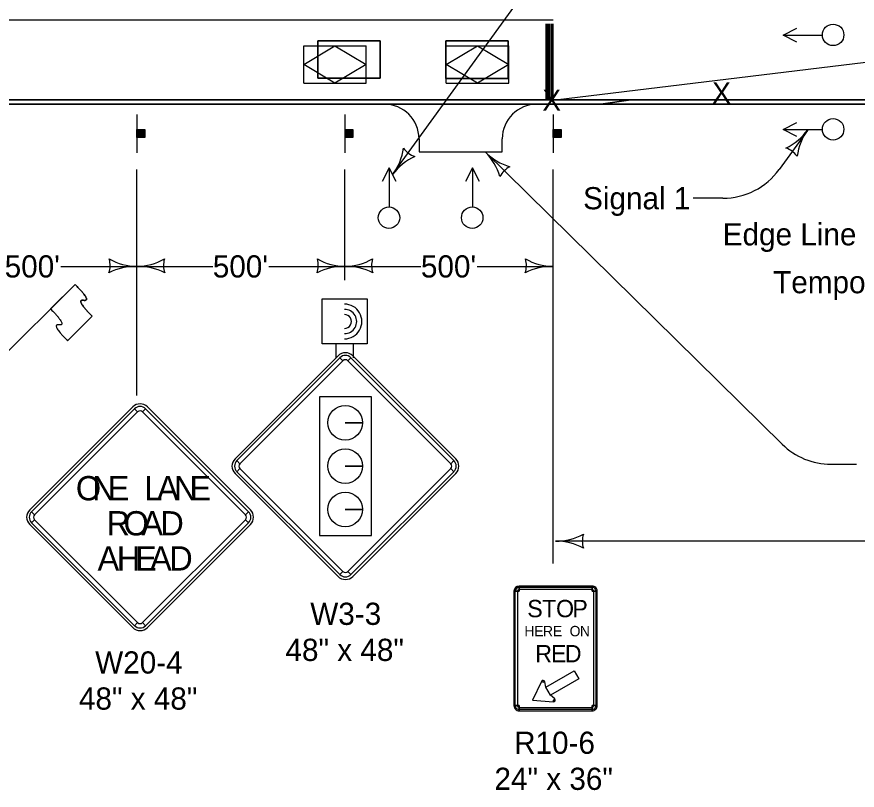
# Model space of a CAD drawing. Extents: x -2134934 to -2122394, y -2139046 to -2137036.
# Drawn here: x -2129918 to -2129313, y -2138163 to -2137605 of the extents above; entities that cross this region are included whole.
import ezdxf

# ---------------------------------------------------------------- set-up
doc = ezdxf.new("R2010")
doc.units = 0
for name, color, linetype in [('Barrier', 7, 'Continuous'), ('BridgeSuperStructureExisting', 7, 'Continuous'), ('DsnShtPlotIdentification', 7, 'Continuous'), ('DsnShtPlotShape', 7, 'Continuous'), ('dsnTextFinalPlan', 7, 'Continuous'), ('TC_Barrier', 7, 'Continuous')]:
    doc.layers.add(name, color=color, linetype=linetype)

msp = doc.modelspace()

# ---------------------------------------------------------------- linework, layer by layer
at = {"layer": 'Barrier'}
for p, q in [((-2129933.82, -2137855.42), (-2129876.5, -2137798.11)), ((-2129876.5, -2137798.11), (-2129894.18, -2137815.79)), ((-2129881.8, -2137838.78), (-2129864.12, -2137821.1)), ((-2129686.95, -2137849.65), (-2129761.19, -2137923.9)), ((-2129685.62, -2137850.98), (-2129683.41, -2137853.19)), ((-2129679.88, -2137853.19), (-2129677.67, -2137850.98)), ((-2129602.1, -2137923.9), (-2129676.34, -2137849.65)), ((-2129834.91, -2137886.48), (-2129909.16, -2137960.72)), ((-2129833.59, -2137887.8), (-2129831.38, -2137890.01)), ((-2129827.84, -2137890.01), (-2129825.63, -2137887.8)), ((-2129750.06, -2137960.72), (-2129824.31, -2137886.48)), ((-2129669.24, -2137897.87), (-2129681.74, -2137897.87)), ((-2129681.74, -2137897.87), (-2129669.24, -2137897.87)), ((-2129757.66, -2137927.43), (-2129759.87, -2137925.22)), ((-2129669.24, -2137929.12), (-2129681.74, -2137929.12)), ((-2129681.74, -2137929.12), (-2129669.24, -2137929.12)), ((-2129603.42, -2137925.22), (-2129605.63, -2137927.43)), ((-2129761.19, -2137934.5), (-2129686.95, -2138008.75)), ((-2129759.87, -2137933.18), (-2129757.66, -2137930.97)), ((-2129676.34, -2138008.75), (-2129602.1, -2137934.5)), ((-2129605.63, -2137930.97), (-2129603.42, -2137933.18)), ((-2129669.24, -2137960.37), (-2129681.74, -2137960.37)), ((-2129681.74, -2137960.37), (-2129669.24, -2137960.37)), ((-2129905.62, -2137964.26), (-2129907.83, -2137962.05)), ((-2129751.39, -2137962.05), (-2129753.59, -2137964.26)), ((-2129909.16, -2137971.33), (-2129834.91, -2138045.58)), ((-2129907.83, -2137970.01), (-2129905.62, -2137967.8)), ((-2129824.31, -2138045.58), (-2129750.06, -2137971.33)), ((-2129753.59, -2137967.8), (-2129751.39, -2137970.01)), ((-2129683.41, -2138005.21), (-2129685.62, -2138007.42)), ((-2129677.67, -2138007.42), (-2129679.88, -2138005.21)), ((-2129560.12, -2138019.4), (-2129556.37, -2138019.4)), ((-2129559.18, -2138019.4), (-2129557.62, -2138019.4)), ((-2129556.37, -2138019.4), (-2129556.37, -2138015.65)), ((-2129556.37, -2138018.15), (-2129556.37, -2138016.58)), ((-2129503.87, -2138015.65), (-2129503.87, -2138019.4)), ((-2129503.87, -2138016.58), (-2129503.87, -2138018.15)), ((-2129503.87, -2138019.4), (-2129500.12, -2138019.4)), ((-2129502.62, -2138019.4), (-2129501.05, -2138019.4)), ((-2129831.38, -2138042.04), (-2129833.59, -2138044.25)), ((-2129825.63, -2138044.25), (-2129827.84, -2138042.04)), ((-2129540.26, -2138084.38), (-2129539.15, -2138084.96)), ((-2129539.15, -2138084.96), (-2129537.93, -2138084.69)), ((-2129531.65, -2138097.95), (-2129531.7, -2138099.2)), ((-2129530.8, -2138097.03), (-2129531.65, -2138097.95)), ((-2129556.37, -2138101.9), (-2129560.12, -2138101.9)), ((-2129557.62, -2138101.9), (-2129559.18, -2138101.9)), ((-2129556.37, -2138105.65), (-2129556.37, -2138101.9)), ((-2129556.37, -2138104.71), (-2129556.37, -2138103.15)), ((-2129500.12, -2138101.9), (-2129503.87, -2138101.9)), ((-2129503.87, -2138101.9), (-2129503.87, -2138105.65)), ((-2129503.87, -2138103.15), (-2129503.87, -2138104.71)), ((-2129501.05, -2138101.9), (-2129502.62, -2138101.9))]:
    msp.add_line(p, q, dxfattribs=at)
for points in [[(-2129685.62, -2137850.98), (-2129759.87, -2137925.22), (-2129757.66, -2137927.43), (-2129683.41, -2137853.19), (-2129685.62, -2137850.98)], [(-2129603.42, -2137925.22), (-2129677.67, -2137850.98), (-2129679.88, -2137853.19), (-2129605.63, -2137927.43), (-2129603.42, -2137925.22)], [(-2129662.91, -2137879.26), (-2129700.38, -2137879.26), (-2129700.38, -2137979.15), (-2129662.91, -2137979.15), (-2129662.91, -2137879.26)], [(-2129833.59, -2137887.8), (-2129907.83, -2137962.05), (-2129905.62, -2137964.26), (-2129831.38, -2137890.01), (-2129833.59, -2137887.8)], [(-2129751.39, -2137962.05), (-2129825.63, -2137887.8), (-2129827.84, -2137890.01), (-2129753.59, -2137964.26), (-2129751.39, -2137962.05)], [(-2129759.87, -2137933.18), (-2129685.62, -2138007.42), (-2129683.41, -2138005.21), (-2129757.66, -2137930.97), (-2129759.87, -2137933.18)], [(-2129677.67, -2138007.42), (-2129603.42, -2137933.18), (-2129605.63, -2137930.97), (-2129679.88, -2138005.21), (-2129677.67, -2138007.42)], [(-2129907.83, -2137970.01), (-2129833.59, -2138044.25), (-2129831.38, -2138042.04), (-2129905.62, -2137967.8), (-2129907.83, -2137970.01)], [(-2129825.63, -2138044.25), (-2129751.39, -2137970.01), (-2129753.59, -2137967.8), (-2129827.84, -2138042.04), (-2129825.63, -2138044.25)], [(-2129556.37, -2138105.65), (-2129503.87, -2138105.65), (-2129503.87, -2138101.9), (-2129500.12, -2138101.9), (-2129500.12, -2138019.4), (-2129503.87, -2138019.4), (-2129503.87, -2138015.65), (-2129556.37, -2138015.65), (-2129556.37, -2138019.4), (-2129560.12, -2138019.4), (-2129560.12, -2138101.9), (-2129556.37, -2138101.9), (-2129556.37, -2138105.65)], [(-2129557.62, -2138019.4), (-2129557.62, -2138101.9), (-2129559.18, -2138101.9), (-2129559.18, -2138019.4), (-2129557.62, -2138019.4)], [(-2129503.87, -2138018.15), (-2129556.37, -2138018.15), (-2129556.37, -2138016.58), (-2129503.87, -2138016.58), (-2129503.87, -2138018.15)], [(-2129502.62, -2138101.9), (-2129502.62, -2138019.4), (-2129501.05, -2138019.4), (-2129501.05, -2138101.9), (-2129502.62, -2138101.9)], [(-2129516.74, -2138076.9), (-2129513.46, -2138082.58), (-2129533.77, -2138094.3), (-2129537.05, -2138088.62), (-2129516.74, -2138076.9)], [(-2129546.77, -2138098.02), (-2129531.7, -2138099.2), (-2129531.65, -2138097.95), (-2129530.8, -2138097.03), (-2129533.77, -2138094.3), (-2129537.05, -2138088.62), (-2129537.93, -2138084.69), (-2129539.15, -2138084.96), (-2129540.26, -2138084.38), (-2129546.77, -2138098.02)], [(-2129556.37, -2138103.15), (-2129503.87, -2138103.15), (-2129503.87, -2138104.71), (-2129556.37, -2138104.71), (-2129556.37, -2138103.15)]]:
    msp.add_lwpolyline(points, close=True, dxfattribs=at)
for centre in [(-2129681.74, -2137897.87), (-2129681.74, -2137929.12), (-2129681.74, -2137960.37)]:
    msp.add_circle(centre, 12.5, dxfattribs=at)
for centre, radius, start, end in [((-2129681.64, -2137854.96), 7.5, 44.99999, 134.99974), ((-2129681.64, -2137854.96), 5.62, 44.99999, 134.99974), ((-2129681.64, -2137854.96), 2.5, 44.99999, 134.99974), ((-2129829.61, -2137891.78), 7.5, 44.99999, 134.99974), ((-2129829.61, -2137891.78), 5.62, 44.99999, 134.99974), ((-2129829.61, -2137891.78), 2.5, 44.99999, 134.99974), ((-2129755.89, -2137929.2), 7.5, 134.99974, 224.99995), ((-2129607.4, -2137929.2), 7.5, 315.00016, 44.9998), ((-2129755.89, -2137929.2), 5.62, 134.99974, 224.99995), ((-2129755.89, -2137929.2), 2.5, 134.99974, 224.99995), ((-2129607.4, -2137929.2), 2.5, 315.00016, 44.9998), ((-2129607.4, -2137929.2), 5.62, 315.00016, 44.9998), ((-2129903.85, -2137966.03), 7.5, 134.99974, 224.99995), ((-2129755.36, -2137966.03), 7.5, 315.00016, 44.9998), ((-2129903.85, -2137966.03), 5.62, 134.99974, 224.99995), ((-2129903.85, -2137966.03), 2.5, 134.99974, 224.99995), ((-2129755.36, -2137966.03), 2.5, 315.00016, 44.9998), ((-2129755.36, -2137966.03), 5.62, 315.00016, 44.9998), ((-2129681.64, -2138003.45), 7.5, 224.99995, 315.00016), ((-2129681.64, -2138003.45), 5.62, 224.99995, 315.00016), ((-2129681.64, -2138003.45), 2.5, 224.99995, 315.00016), ((-2129556.37, -2138019.4), 3.75, 90.00021, 179.99985), ((-2129556.37, -2138019.4), 2.81, 90.00021, 179.99985), ((-2129556.37, -2138019.4), 1.25, 90.00021, 179.99985), ((-2129503.87, -2138019.4), 3.75, 0, 90.00021), ((-2129503.87, -2138019.4), 2.81, 0, 90.00021), ((-2129503.87, -2138019.4), 1.25, 0, 90.00021), ((-2129829.61, -2138040.27), 5.62, 224.99995, 315.00016), ((-2129829.61, -2138040.27), 2.5, 224.99995, 315.00016), ((-2129829.61, -2138040.27), 7.5, 224.99995, 315.00016), ((-2129539.15, -2138084.96), 1.25, 12.62232, 152.27557), ((-2129531.65, -2138097.95), 1.25, 267.72427, 47.37758), ((-2129556.37, -2138101.9), 3.75, 179.99985, 270.00006), ((-2129556.37, -2138101.9), 2.81, 179.99985, 270.00006), ((-2129556.37, -2138101.9), 1.25, 179.99985, 270.00006), ((-2129503.87, -2138101.9), 3.75, 270.00006, 0.00027), ((-2129503.87, -2138101.9), 2.81, 270.00006, 0.00027), ((-2129503.87, -2138101.9), 1.25, 270.00006, 0.00027)]:
    msp.add_arc(centre, radius, start, end, dxfattribs=at)
for points in [[(-2129864.12, -2137821.1), (-2129876.5, -2137808.72), (-2129864.12, -2137810.49), (-2129876.5, -2137798.11)], [(-2129894.18, -2137815.79), (-2129881.8, -2137828.17), (-2129894.17, -2137826.4), (-2129881.8, -2137838.78)]]:
    msp.add_open_spline(points, degree=2, dxfattribs=at)
at = {"layer": 'BridgeSuperStructureExisting'}
for p, q in [((-2129647.56, -2137718.98), (-2129506.09, -2137523.28)), ((-2129530.12, -2137665.16), (-2129039.8, -2137605.17)), ((-2129536.95, -2137665.16), (-2129536.95, -2137610.16)), ((-2129535.95, -2137665.16), (-2129535.95, -2137610.16)), ((-2129534.95, -2137665.16), (-2129534.95, -2137610.16)), ((-2129533.95, -2137665.16), (-2129533.95, -2137610.16)), ((-2129532.95, -2137665.16), (-2129532.95, -2137610.16)), ((-2129531.95, -2137665.16), (-2129531.95, -2137610.16)), ((-2129337.85, -2137618.58), (-2129365.8, -2137618.58)), ((-2129711.63, -2137653.13), (-2129711.63, -2137626.13)), ((-2129711.63, -2137626.13), (-2129666.63, -2137626.13)), ((-2129701.47, -2137622.46), (-2129656.47, -2137622.46)), ((-2129701.47, -2137649.46), (-2129701.47, -2137622.46)), ((-2129656.47, -2137622.46), (-2129701.47, -2137622.46)), ((-2129701.47, -2137622.46), (-2129701.47, -2137649.46)), ((-2129666.63, -2137653.13), (-2129666.63, -2137626.13)), ((-2129656.47, -2137622.46), (-2129656.47, -2137649.46)), ((-2129656.47, -2137649.46), (-2129656.47, -2137622.46)), ((-2129609.28, -2137622.54), (-2129564.28, -2137622.54)), ((-2129609.28, -2137649.54), (-2129609.28, -2137622.54)), ((-2129564.28, -2137622.54), (-2129609.28, -2137622.54)), ((-2129609.28, -2137622.54), (-2129609.28, -2137649.54)), ((-2129608.95, -2137653.13), (-2129608.95, -2137626.13)), ((-2129608.95, -2137626.13), (-2129563.95, -2137626.13)), ((-2129564.28, -2137622.54), (-2129564.28, -2137649.54)), ((-2129564.28, -2137649.54), (-2129564.28, -2137622.54)), ((-2129563.95, -2137653.13), (-2129563.95, -2137626.13)), ((-2129656.47, -2137649.46), (-2129701.47, -2137649.46)), ((-2129701.47, -2137649.46), (-2129656.47, -2137649.46)), ((-2129564.28, -2137649.54), (-2129609.28, -2137649.54)), ((-2129609.28, -2137649.54), (-2129564.28, -2137649.54)), ((-2129711.63, -2137653.13), (-2129666.63, -2137653.13)), ((-2129608.95, -2137653.13), (-2129563.95, -2137653.13)), ((-2130182.57, -2137665.16), (-2128870.12, -2137665.16)), ((-2129543.56, -2137668.16), (-2129653.56, -2137668.16)), ((-2129639.46, -2137668.16), (-2129614.46, -2137668.16)), ((-2129831.95, -2137675.66), (-2129831.95, -2137703.16)), ((-2129681.95, -2137675.66), (-2129681.95, -2137703.16)), ((-2129531.95, -2137675.66), (-2129531.95, -2137703.16)), ((-2129831.54, -2137692.11), (-2129831.54, -2137686.52)), ((-2129831.26, -2137686.52), (-2129831.26, -2137692.11)), ((-2129830.99, -2137692.11), (-2129830.99, -2137686.52)), ((-2129830.73, -2137686.52), (-2129830.73, -2137692.11)), ((-2129830.51, -2137692.11), (-2129830.51, -2137686.52)), ((-2129830.3, -2137686.52), (-2129830.3, -2137692.11)), ((-2129829.96, -2137692.11), (-2129829.96, -2137686.52)), ((-2129829.7, -2137686.52), (-2129829.7, -2137692.11)), ((-2129829.47, -2137692.11), (-2129829.49, -2137686.52)), ((-2129829.16, -2137686.52), (-2129829.16, -2137692.11)), ((-2129828.78, -2137692.11), (-2129828.78, -2137686.52)), ((-2129828.35, -2137686.52), (-2129828.35, -2137692.11)), ((-2129828.12, -2137692.11), (-2129828.14, -2137686.52)), ((-2129827.71, -2137686.52), (-2129827.69, -2137692.11)), ((-2129827.49, -2137692.11), (-2129827.49, -2137686.52)), ((-2129827.17, -2137686.52), (-2129827.17, -2137692.11)), ((-2129826.94, -2137692.11), (-2129826.94, -2137686.52)), ((-2129826.62, -2137686.52), (-2129826.62, -2137692.11)), ((-2129681.54, -2137692.11), (-2129681.54, -2137686.52)), ((-2129681.26, -2137686.52), (-2129681.26, -2137692.11)), ((-2129680.99, -2137692.11), (-2129680.99, -2137686.52)), ((-2129680.73, -2137686.52), (-2129680.73, -2137692.11)), ((-2129680.51, -2137692.11), (-2129680.51, -2137686.52)), ((-2129680.3, -2137686.52), (-2129680.3, -2137692.11)), ((-2129679.96, -2137692.11), (-2129679.96, -2137686.52)), ((-2129679.7, -2137686.52), (-2129679.7, -2137692.11)), ((-2129679.48, -2137692.11), (-2129679.49, -2137686.52)), ((-2129679.16, -2137686.52), (-2129679.16, -2137692.11)), ((-2129678.78, -2137692.11), (-2129678.78, -2137686.52)), ((-2129678.35, -2137686.52), (-2129678.35, -2137692.11)), ((-2129678.13, -2137692.11), (-2129678.14, -2137686.52)), ((-2129677.71, -2137686.52), (-2129677.69, -2137692.11)), ((-2129677.49, -2137692.11), (-2129677.49, -2137686.52)), ((-2129677.17, -2137686.52), (-2129677.17, -2137692.11)), ((-2129676.94, -2137692.11), (-2129676.94, -2137686.52)), ((-2129676.63, -2137686.52), (-2129676.63, -2137692.11)), ((-2129531.54, -2137692.11), (-2129531.54, -2137686.52)), ((-2129531.26, -2137686.52), (-2129531.26, -2137692.11)), ((-2129530.99, -2137692.11), (-2129530.99, -2137686.52)), ((-2129530.73, -2137686.52), (-2129530.73, -2137692.11)), ((-2129530.51, -2137692.11), (-2129530.51, -2137686.52)), ((-2129530.3, -2137686.52), (-2129530.3, -2137692.11)), ((-2129529.96, -2137692.11), (-2129529.96, -2137686.52)), ((-2129529.7, -2137686.52), (-2129529.7, -2137692.11)), ((-2129529.48, -2137692.11), (-2129529.49, -2137686.52)), ((-2129529.16, -2137686.52), (-2129529.16, -2137692.11)), ((-2129528.78, -2137692.11), (-2129528.78, -2137686.52)), ((-2129528.35, -2137686.52), (-2129528.35, -2137692.11)), ((-2129528.13, -2137692.11), (-2129528.14, -2137686.52)), ((-2129527.71, -2137686.52), (-2129527.69, -2137692.11)), ((-2129527.49, -2137692.11), (-2129527.49, -2137686.52)), ((-2129527.17, -2137686.52), (-2129527.17, -2137692.11)), ((-2129526.94, -2137692.11), (-2129526.94, -2137686.52)), ((-2129526.63, -2137686.52), (-2129526.63, -2137692.11)), ((-2129348.66, -2137687.16), (-2129368.99, -2137715.28)), ((-2129337.85, -2137686.64), (-2129365.8, -2137686.64)), ((-2129366.79, -2137913.4), (-2129580.78, -2137702.65)), ((-2129831.95, -2137878.33), (-2129831.95, -2137715.16)), ((-2129681.95, -2137795.16), (-2129681.95, -2137715.16)), ((-2129649.88, -2137742.3), (-2129649.88, -2137714.35)), ((-2129589.88, -2137742.3), (-2129589.88, -2137714.35)), ((-2129531.95, -2137999.46), (-2129531.95, -2137715.16)), ((-2129409.51, -2137735.99), (-2129430.88, -2137735.99)), ((-2129886.7, -2137785.16), (-2129831.95, -2137785.16)), ((-2129831.95, -2137785.16), (-2129777.2, -2137785.16)), ((-2129736.7, -2137785.16), (-2129681.95, -2137785.16)), ((-2129681.95, -2137785.16), (-2129627.2, -2137785.16)), ((-2129586.7, -2137785.16), (-2129531.95, -2137785.16)), ((-2129688.49, -2137841.1), (-2129688.49, -2137851.1)), ((-2129675.99, -2137841.1), (-2129675.99, -2137851.1)), ((-2129331.71, -2137927.78), (-2129313.25, -2137927.78)), ((-2128866.54, -2137983.33), (-2129530.12, -2137983.33))]:
    msp.add_line(p, q, dxfattribs=at)
for points in [[(-2129356.17, -2137623.39), (-2129366.17, -2137618.39), (-2129356.17, -2137613.39)], [(-2129356.17, -2137691.45), (-2129366.17, -2137686.45), (-2129356.17, -2137681.45)], [(-2129628.56, -2137693.16), (-2129628.56, -2137702.65), (-2129568.56, -2137702.65), (-2129568.56, -2137693.16)], [(-2129645.06, -2137723.98), (-2129650.06, -2137713.98), (-2129655.06, -2137723.98)], [(-2129585.06, -2137723.98), (-2129590.06, -2137713.98), (-2129595.06, -2137723.98)]]:
    msp.add_lwpolyline(points, dxfattribs=at)
for points in [[(-2129831.86, -2137692.11), (-2129831.86, -2137686.48), (-2129826.23, -2137686.48), (-2129826.23, -2137692.11)], [(-2129681.86, -2137692.11), (-2129681.86, -2137686.48), (-2129676.23, -2137686.48), (-2129676.23, -2137692.11)], [(-2129531.86, -2137692.11), (-2129531.86, -2137686.48), (-2129526.23, -2137686.48), (-2129526.23, -2137692.11)], [(-2129698.49, -2137841.1), (-2129698.49, -2137808.6), (-2129665.99, -2137808.6), (-2129665.99, -2137841.1)]]:
    msp.add_lwpolyline(points, close=True, dxfattribs=at)
for centre in [(-2129330.12, -2137618.21), (-2129330.12, -2137686.27), (-2129650.24, -2137750.03), (-2129590.24, -2137750.03)]:
    msp.add_circle(centre, 7.74, dxfattribs=at)
for centre, radius, start, end in [((-2129653.56, -2137693.16), 25, 0, 90), ((-2129543.56, -2137693.16), 25, 90, 180), ((-2129409.51, -2137685.99), 50, 270, 324.13795), ((-2129867.57, -2137784.54), 16.42, 341.26665, 16.73335), ((-2129831.2, -2137742.67), 42.5, 240.92751, 268.9824), ((-2129832.71, -2137742.67), 42.5, 271.0176, 299.07249), ((-2129796.33, -2137784.54), 16.42, 163.26665, 198.73335), ((-2129717.57, -2137784.54), 16.42, 341.26665, 16.73335), ((-2129681.2, -2137742.67), 42.5, 240.92751, 268.9824), ((-2129682.71, -2137742.67), 42.5, 271.0176, 299.07249), ((-2129646.33, -2137784.54), 16.42, 163.26665, 198.73335), ((-2129567.57, -2137784.54), 16.42, 341.26665, 16.73335), ((-2129531.2, -2137742.67), 42.5, 240.92751, 268.9824), ((-2129832.68, -2137827.65), 42.5, 89.0176, 117.07249), ((-2129831.22, -2137827.65), 42.5, 62.92751, 90.9824), ((-2129682.68, -2137827.65), 42.5, 89.0176, 117.07249), ((-2129681.22, -2137827.65), 42.5, 62.92751, 90.9824), ((-2129532.68, -2137827.65), 42.5, 89.0176, 117.07249), ((-2129682.23, -2137824.87), 12.5, 269.40414, 90.54446), ((-2129682.23, -2137824.87), 12.5, 269.40414, 90.54446), ((-2129682.23, -2137824.87), 8.75, 269.40414, 90.54446), ((-2129682.23, -2137824.87), 5, 269.40414, 90.54446), ((-2129331.71, -2137877.78), 50, 225.43651, 270)]:
    msp.add_arc(centre, radius, start, end, dxfattribs=at)
at = {"layer": 'DsnShtPlotIdentification'}
for p, q in [((-2129531.95, -2137607.66), (-2130184.45, -2137607.66)), ((-2129535.12, -2137665.16), (-2130182.57, -2137665.16)), ((-2130182.57, -2137668.16), (-2129497.55, -2137668.16)), ((-2130181.95, -2137665.16), (-2128681.95, -2137665.16)), ((-2129475.87, -2137665.16), (-2129530.12, -2137665.16)), ((-2129497.55, -2137668.16), (-2129475.87, -2137665.16)), ((-2129475.87, -2137665.16), (-2129497.55, -2137668.16)), ((-2129497.55, -2137668.16), (-2129183.89, -2137668.16)), ((-2129182.92, -2137665.16), (-2129475.87, -2137665.16))]:
    msp.add_line(p, q, dxfattribs=at)
for points in [[(-2128870.12, -2137665.16), (-2130182.57, -2137665.16)], [(-2128870.12, -2137668.16), (-2130182.57, -2137668.16)], [(-2129532.12, -2137665.16), (-2129533.12, -2137665.16), (-2129534.12, -2137665.16), (-2129535.12, -2137665.16)], [(-2129530.12, -2137665.16), (-2129531.12, -2137665.16), (-2129532.12, -2137665.16)]]:
    msp.add_lwpolyline(points, dxfattribs=at)
at = {"layer": 'DsnShtPlotShape'}
for centre, radius, start, end in [((-2129382.54, -2137661.48), 42.5, 295.62849, 323.70098), ((-2129314.03, -2137711.8), 42.5, 143.70098, 171.77347), ((-2129681.81, -2137693.82), 42.5, 323.70098, 351.77347), ((-2129626.47, -2137690.26), 16.42, 215.96763, 251.43433), ((-2129369.38, -2137715.36), 16.42, 35.96763, 71.43433), ((-2129613.31, -2137744.14), 42.5, 115.62849, 143.70098), ((-2129610.97, -2137732.56), 42.5, 16.65786, 44.73035), ((-2129550.58, -2137672.74), 42.5, 224.73035, 252.80284), ((-2129555.7, -2137727.96), 16.42, 116.997, 152.46371), ((-2129530.12, -2137940.83), 42.5, 270, 298.07249), ((-2129494.48, -2137983.33), 16.42, 162.26665, 197.73335), ((-2129530.12, -2138025.83), 42.5, 61.92751, 90)]:
    msp.add_arc(centre, radius, start, end, dxfattribs=at)
at = {"layer": 'dsnTextFinalPlan'}
for points in [[(-2129711.63, -2137639.63), (-2129689.13, -2137626.13), (-2129666.63, -2137639.63), (-2129689.13, -2137653.13)], [(-2129608.95, -2137639.63), (-2129586.45, -2137626.13), (-2129563.95, -2137639.63), (-2129586.45, -2137653.13)]]:
    msp.add_lwpolyline(points, close=True, dxfattribs=at)
at = {"layer": 'TC_Barrier'}
msp.add_line((-2129864.12, -2137821.1), (-2129881.8, -2137838.78), dxfattribs=at)
for points in [[(-2129876.5, -2137798.11), (-2129864.12, -2137810.49), (-2129876.5, -2137808.72), (-2129864.12, -2137821.1)], [(-2129894.18, -2137815.79), (-2129881.8, -2137828.17), (-2129894.17, -2137826.4), (-2129881.8, -2137838.78)]]:
    msp.add_open_spline(points, degree=2, dxfattribs=at)

# ---------------------------------------------------------------- texts
at = {"layer": 'Barrier'}
for s, height, p in [('O', 17.5, (-2129875.89, -2137953.84)), ('N', 17.5, (-2129864.12, -2137953.84)), ('E', 17.5, (-2129852.89, -2137953.84)), ('L', 17.5, (-2129826.64, -2137953.84)), ('A', 17.5, (-2129817.44, -2137953.84)), ('N', 17.5, (-2129805.18, -2137953.84)), ('E', 17.5, (-2129793.95, -2137953.84)), ('R', 17.5, (-2129853.79, -2137979.15)), ('O', 17.5, (-2129841.5, -2137979.15)), ('A', 17.5, (-2129828.66, -2137979.15)), ('D', 17.5, (-2129815, -2137979.15)), ('A', 17.5, (-2129860.22, -2138004.47)), ('H', 17.5, (-2129846.36, -2138004.47)), ('E', 17.5, (-2129833.14, -2138004.47)), ('A', 17.5, (-2129822.43, -2138004.47)), ('D', 17.5, (-2129808.56, -2138004.47)), ('S', 12.5, (-2129550.56, -2138038.15)), ('T', 12.5, (-2129539.8, -2138038.15)), ('O', 12.5, (-2129529.81, -2138038.15)), ('P', 12.5, (-2129518.07, -2138038.15)), ('W3-3', 16, (-2129706.94, -2138043.67)), ('H', 7.5, (-2129552.64, -2138051.9)), ('E', 7.5, (-2129545.49, -2138051.9)), ('R', 7.5, (-2129539.23, -2138051.9)), ('E', 7.5, (-2129532.08, -2138051.9)), ('O', 7.5, (-2129520.01, -2138051.9)), ('N', 7.5, (-2129512.63, -2138051.9)), ('48" x 48"', 16, (-2129724.81, -2138069.67)), ('W20-4', 16, (-2129861.97, -2138078.77)), ('R', 12.5, (-2129544.8, -2138070.65)), ('E', 12.5, (-2129533.47, -2138070.65)), ('D', 12.5, (-2129523.51, -2138070.65)), ('48" x 48"', 16, (-2129873.68, -2138104.77)), ('R10-6', 16, (-2129560.04, -2138136.65)), ('24" x 36"', 16, (-2129574.18, -2138162.65))]:
    msp.add_text(s, height=height, dxfattribs=at).set_placement(p)
at = {"layer": 'BridgeSuperStructureExisting'}
for s, height, p in [('X', 15, (-2129539.63, -2137672.81)), ('Signal 1', 16, (-2129510.31, -2137743.99)), ('Edge Line', 16, (-2129409.67, -2137769.99)), ("500'", 16, (-2129927.2, -2137793.16)), ("500'", 16, (-2129777.2, -2137793.16)), ("500'", 16, (-2129627.2, -2137793.16)), ('Temporary Crash Cushion', 16, (-2129373.33, -2137804.53))]:
    msp.add_text(s, height=height, dxfattribs=at).set_placement(p)
msp.add_text('X', height=15, rotation=359.96521, dxfattribs=at).set_placement((-2129417.24, -2137667.48))

doc.saveas('drawing.dxf')
